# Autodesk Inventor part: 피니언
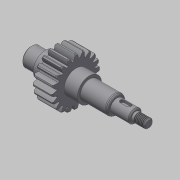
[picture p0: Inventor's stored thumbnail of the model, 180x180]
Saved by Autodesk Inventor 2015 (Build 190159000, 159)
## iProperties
Created: 2019-06
Part Number: 피니언
Material: 스테인리스강
Document SubType Name: Modeling
Designer: mduedu
Density: 1 g/cm^3
Appearance: 기본값
Author: mduedu
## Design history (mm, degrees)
sketch "스케치1"
  geometry: L1 (0, 0)-(13, 0); L2 (13, 0)-(13, 8.5); L3 (13, 8.5)-(0, 8.5); L4 (0, 8.5)-(0, 0); L5 (13, 0)-(53, 0); L6 (53, 0)-(53, 11); L7 (53, 11)-(13, 11); L8 (13, 11)-(13, 0); L9 (53, 0)-(78, 0); L10 (78, 0)-(78, 8.5); L11 (78, 8.5)-(53, 8.5); L12 (53, 8.5)-(53, 0); L13 (78, 0)-(95, 0); L14 (95, 0)-(95, 6); L15 (95, 6)-(78, 6); L16 (78, 6)-(78, 0); L17 (95, 0)-(107, 0); L18 (107, 0)-(107, 4); L19 (107, 4)-(95, 4); L20 (95, 4)-(95, 0)
  constraints: 40 end point, 10 parallel, 5 horizontal, 5 perpendicular
  dimensions: "d0" = 107 distance between parallel lines of L18 L4; "d2" = 78 distance between parallel lines of L10 L4; "d3" = 40 distance of L6.end L7.end; "d4" = 25 distance of L10.end L11.end; "d5" = 17 distance of L14.end L15.end; "d6" = 8 diameter of L19 L17; "d7" = 12 diameter of L15 L13; "d8" = 17 diameter of L11 L9; "d9" = 22 diameter of L7 L5; "d10" = 17 diameter of L3 L1
revolve "회전1" sketch "스케치1" stored, may be unused: angle "d11" = 90 deg
node "작업 평면1"
sketch "스케치2"
  geometry: C1 r 17.5 at (0, 0); C2 r 20 at (0, 0); C3 r 22 at (0, 0); 1 further point
  constraints: 3 centre point, 3 coincident
  dimensions: "d13" = 40 diameter of C2; "d15" = 44 diameter of C3; "d16" = 35 diameter of C1
extrude "돌출1" join sketch "스케치2" distance "d17" = 18; taper "d18" = 0 deg
sketch "스케치3"
  geometry: L1 (0, 0)-(22, 0); L2 (0, 0)-(0, 22); L3 (0.57, 0)-(0.57, 22); L4 (1.57, 0)-(1.57, 22); L5 (2.07, 0)-(2.07, 22); A1 r 22 centre (0, 0) between (22, 0) and (0, 22) reference; A2 r 9.495 centre (-7.411, 16.856) between (2.07, 17.377) and (0.57, 22); A3 r 9.495 centre (7.411, 16.856) between (-0.57, 22) and (-2.07, 17.377); A4 r 17.5 centre (0, 0) between (2.07, 17.377) and (-2.07, 17.377); A5 r 22.007 centre (0, 0) between (0.57, 22) and (-0.57, 22); 4 further points
  constraints: 11 point on circle, 10 end point, 6 parallel, 5 point on line, 4 centre point, 3 symmetric about line, 2 coincident, 1 horizontal, 1 perpendicular, 5 other
  dimensions: "d19" = 0.5 distance between parallel lines of L5 L4; "d21" = 1 distance between parallel lines of L3 L4; "d22" = 1.57 distance between parallel lines of L2 L4
extrude "돌출2" join sketch "스케치3" stored distance "d23" = 18; taper "d24" = 0 deg
chamfer "모따기1" distance "d25" = 1; stored, may be unused: second distance "d26" = 2, angle "d27" = 45 deg
fillet "모깎기1" dims "d31" = 0.3
chamfer "모따기2" distance "d32" = 1; stored, may be unused: second distance "d33" = 2, angle "d34" = 45 deg
node "작업 평면2"
sketch "스케치4"
  geometry: L1 (3.5, -2)-(-2.5, -2); L2 (-2.5, 2)-(3.5, 2); L3 (8.5, 8.5)-(8.5, -8.5) reference; A1 r 2 centre (3.5, 0) between (3.5, -2) and (3.5, 2); A2 r 2 centre (-2.5, 0) between (-2.5, 2) and (-2.5, -2); 1 further point
  constraints: 4 end point, 4 point on circle, 4 tangent, 2 centre point, 1 horizontal, 1 horizontal alignment, 1 parallel
  dimensions: "d35" = 3 distance edge to line of A1 L3; "d36" = 10 dimension on A2 A1; "d37" = 4 distance between parallel lines of L2 L1
extrude "돌출3" cut sketch "스케치4" distance "d38" = 2.5; taper "d39" = 0 deg
chamfer "모따기3" distance "d40" = 1.82; stored, may be unused: second distance "d41" = 2, angle "d42" = 30 deg
fillet "모깎기2" dims "d43" = 1, "d44" = 2
chamfer "모따기4" distance "d45" = 1; stored, may be unused: second distance "d46" = 2, angle "d47" = 30 deg
feature "스레드1" dims "d48" = 10, "d49" = 0
chamfer "모따기5" distance "d50" = 1; stored, may be unused: second distance "d51" = 2, angle "d52" = 30 deg
node "솔리드1"
pattern_circular "원형 패턴1" dims angle "d29" = 360 deg
other parameters: "d12" = -12
